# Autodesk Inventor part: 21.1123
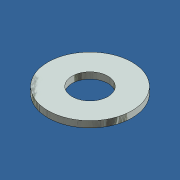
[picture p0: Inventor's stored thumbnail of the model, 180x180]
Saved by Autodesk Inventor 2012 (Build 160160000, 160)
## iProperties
Created: 2007-04
Part Number: 21.1123
Material: Steel
Document SubType Name: Modeling
Designer: Andy Moles
Density: 7.85 g/cm^3
Mass: 3.03105 g
Surface Area: 6.49132 cm^2
Volume: 0.386121 cm^3
Description: WASHER M8 ROUND O.D. 20mm
Vendor: S
Author: Andy Moles
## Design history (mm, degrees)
sketch "Sketch1"
  geometry: C1 r 4.25 at (0, 0); C2 r 10 at (0, 0); 1 further point
  constraints: 2 centre point, 2 coincident
  dimensions: "d0" = 8.5 diameter of C1; "d1" = 20 diameter of C2
extrude "Extrusion1" new body sketch "Sketch1" distance "d2" = 1.5; taper "d3" = 0 deg
body "Solid1"
